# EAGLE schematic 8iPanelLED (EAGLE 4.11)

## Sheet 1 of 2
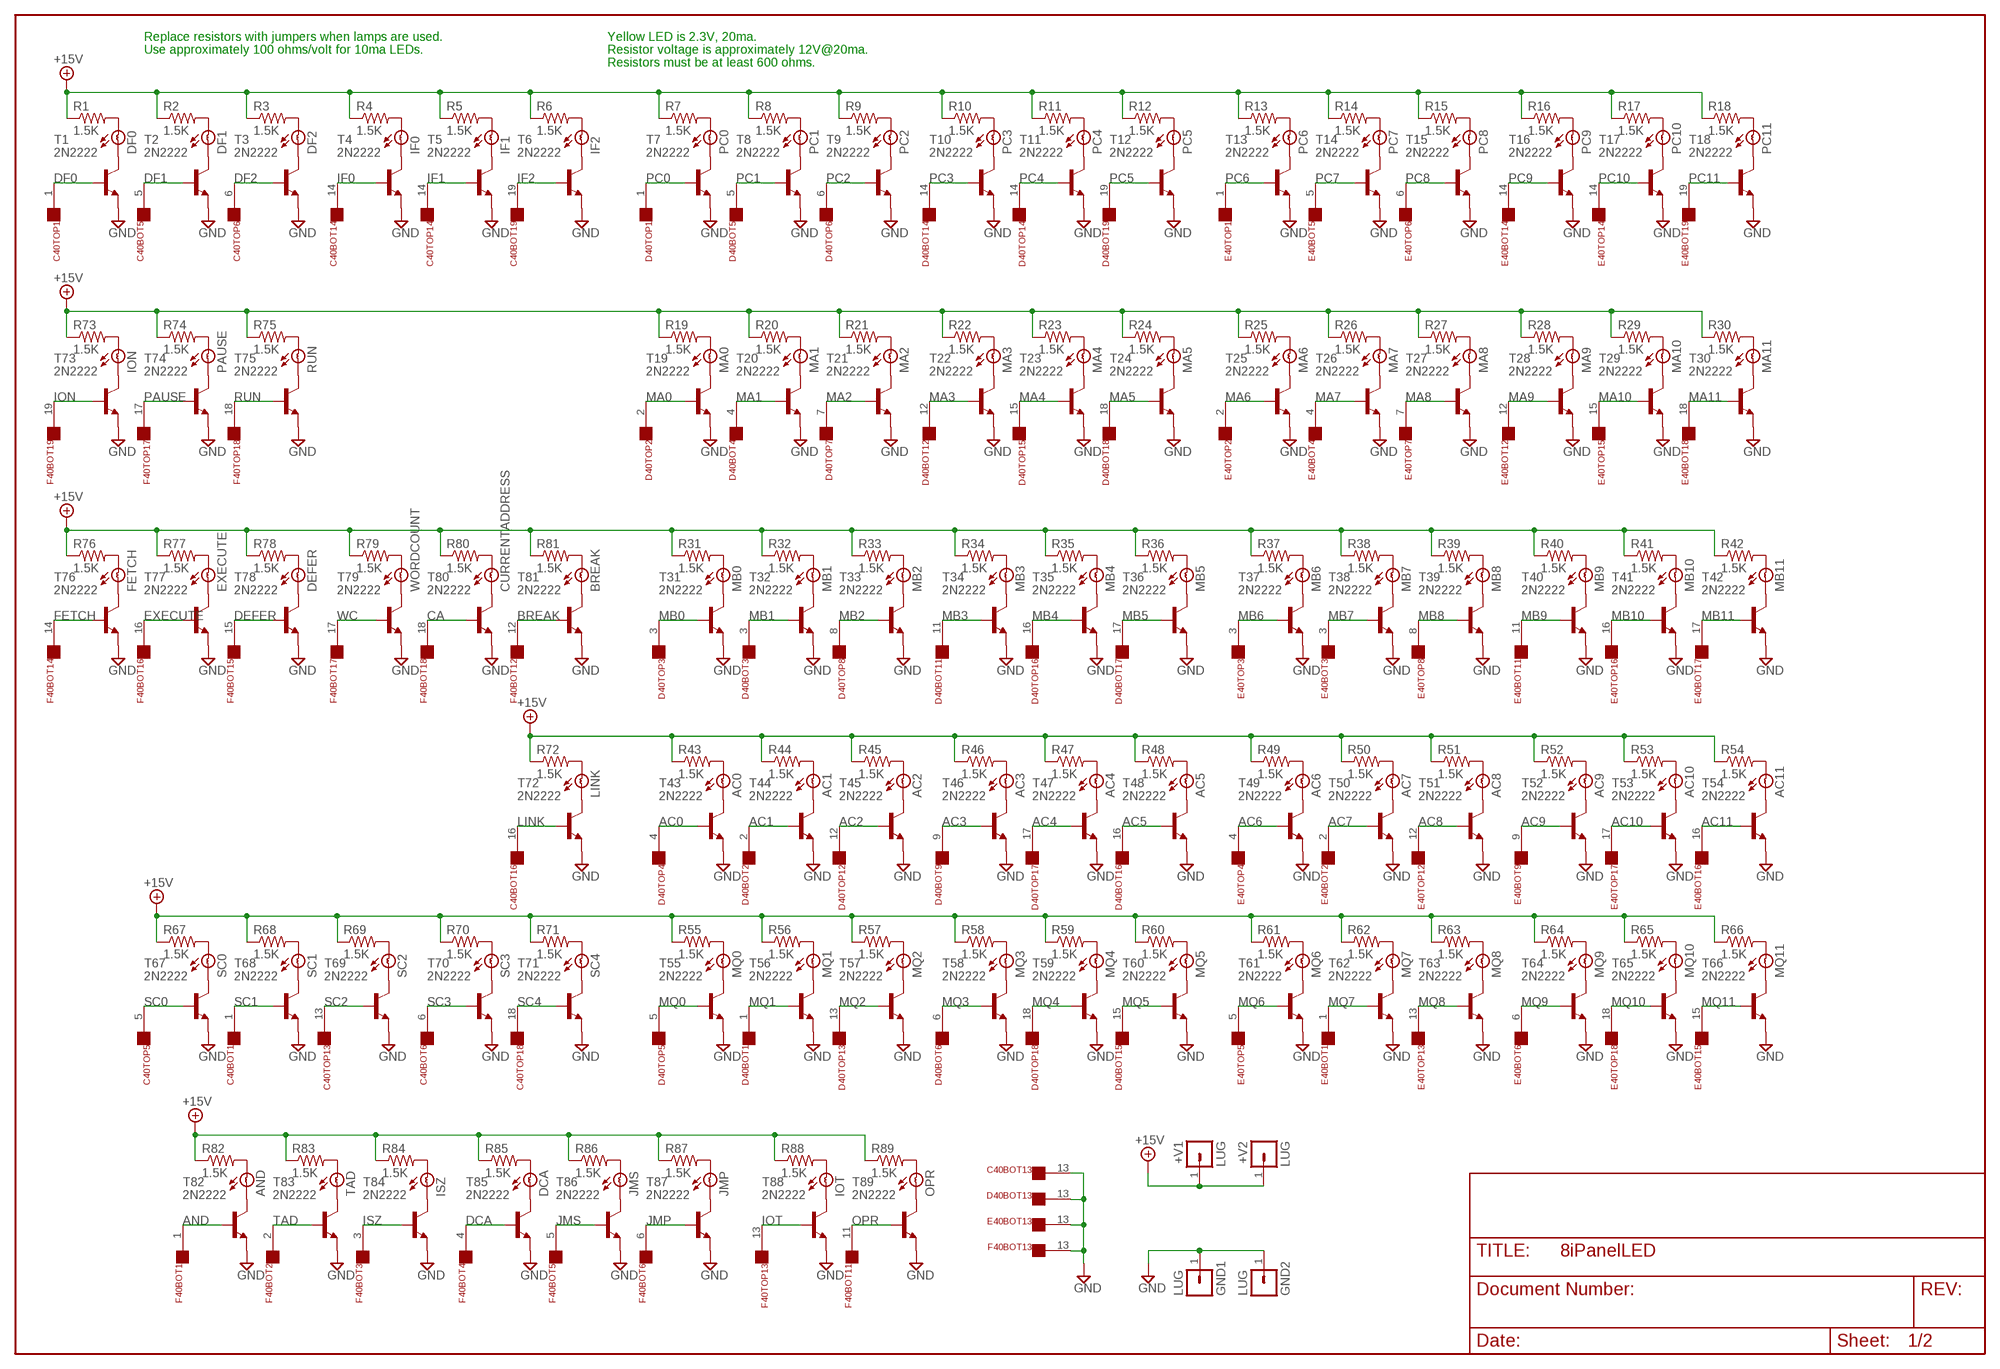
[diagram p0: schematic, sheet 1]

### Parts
+V1  LUG  [SPADELUG]
+V2  LUG  [SPADELUG]
AC0  BULB  [BULB]
AC1  BULB  [BULB]
AC2  BULB  [BULB]
AC3  BULB  [BULB]
AC4  BULB  [BULB]
AC5  BULB  [BULB]
AC6  BULB  [BULB]
AC7  BULB  [BULB]
AC8  BULB  [BULB]
AC9  BULB  [BULB]
AC10  BULB  [BULB]
AC11  BULB  [BULB]
AND  BULB  [BULB]
BREAK  BULB  [BULB]
C40BOT  FLEX19  [FLEX19]
C40TOP  FLEX19  [FLEX19]
CURRENTADDRESS  BULB  [BULB]
D40BOT  FLEX19  [FLEX19]
D40TOP  FLEX19  [FLEX19]
DCA  BULB  [BULB]
DEFER  BULB  [BULB]
DF0  BULB  [BULB]
DF1  BULB  [BULB]
DF2  BULB  [BULB]
E40BOT  FLEX19  [FLEX19]
E40TOP  FLEX19  [FLEX19]
EXECUTE  BULB  [BULB]
F40BOT  FLEX19  [FLEX19]
F40TOP  FLEX19  [FLEX19]
FETCH  BULB  [BULB]
GND1  LUG  [SPADELUG]
GND2  LUG  [SPADELUG]
IF0  BULB  [BULB]
IF1  BULB  [BULB]
IF2  BULB  [BULB]
ION  BULB  [BULB]
IOT  BULB  [BULB]
ISZ  BULB  [BULB]
JMP  BULB  [BULB]
JMS  BULB  [BULB]
LINK  BULB  [BULB]
MA0  BULB  [BULB]
MA1  BULB  [BULB]
MA2  BULB  [BULB]
MA3  BULB  [BULB]
MA4  BULB  [BULB]
MA5  BULB  [BULB]
MA6  BULB  [BULB]
MA7  BULB  [BULB]
MA8  BULB  [BULB]
MA9  BULB  [BULB]
MA10  BULB  [BULB]
MA11  BULB  [BULB]
MB0  BULB  [BULB]
MB1  BULB  [BULB]
MB2  BULB  [BULB]
MB3  BULB  [BULB]
MB4  BULB  [BULB]
MB5  BULB  [BULB]
MB6  BULB  [BULB]
MB7  BULB  [BULB]
MB8  BULB  [BULB]
MB9  BULB  [BULB]
MB10  BULB  [BULB]
MB11  BULB  [BULB]
MQ0  BULB  [BULB]
MQ1  BULB  [BULB]
MQ2  BULB  [BULB]
MQ3  BULB  [BULB]
MQ4  BULB  [BULB]
MQ5  BULB  [BULB]
MQ6  BULB  [BULB]
MQ7  BULB  [BULB]
MQ8  BULB  [BULB]
MQ9  BULB  [BULB]
MQ10  BULB  [BULB]
MQ11  BULB  [BULB]
OPR  BULB  [BULB]
PAUSE  BULB  [BULB]
PC0  BULB  [BULB]
PC1  BULB  [BULB]
PC2  BULB  [BULB]
PC3  BULB  [BULB]
PC4  BULB  [BULB]
PC5  BULB  [BULB]
PC6  BULB  [BULB]
PC7  BULB  [BULB]
PC8  BULB  [BULB]
PC9  BULB  [BULB]
PC10  BULB  [BULB]
PC11  BULB  [BULB]
R1  1.5K  R-US_0207/10  [0207/10]
R2  1.5K  R-US_0207/10  [0207/10]
R3  1.5K  R-US_0207/10  [0207/10]
R4  1.5K  R-US_0207/10  [0207/10]
R5  1.5K  R-US_0207/10  [0207/10]
R6  1.5K  R-US_0207/10  [0207/10]
R7  1.5K  R-US_0207/10  [0207/10]
R8  1.5K  R-US_0207/10  [0207/10]
R9  1.5K  R-US_0207/10  [0207/10]
R10  1.5K  R-US_0207/10  [0207/10]
R11  1.5K  R-US_0207/10  [0207/10]
R12  1.5K  R-US_0207/10  [0207/10]
R13  1.5K  R-US_0207/10  [0207/10]
R14  1.5K  R-US_0207/10  [0207/10]
R15  1.5K  R-US_0207/10  [0207/10]
R16  1.5K  R-US_0207/10  [0207/10]
R17  1.5K  R-US_0207/10  [0207/10]
R18  1.5K  R-US_0207/10  [0207/10]
R19  1.5K  R-US_0207/10  [0207/10]
R20  1.5K  R-US_0207/10  [0207/10]
R21  1.5K  R-US_0207/10  [0207/10]
R22  1.5K  R-US_0207/10  [0207/10]
R23  1.5K  R-US_0207/10  [0207/10]
R24  1.5K  R-US_0207/10  [0207/10]
R25  1.5K  R-US_0207/10  [0207/10]
R26  1.5K  R-US_0207/10  [0207/10]
R27  1.5K  R-US_0207/10  [0207/10]
R28  1.5K  R-US_0207/10  [0207/10]
R29  1.5K  R-US_0207/10  [0207/10]
R30  1.5K  R-US_0207/10  [0207/10]
R31  1.5K  R-US_0207/10  [0207/10]
R32  1.5K  R-US_0207/10  [0207/10]
R33  1.5K  R-US_0207/10  [0207/10]
R34  1.5K  R-US_0207/10  [0207/10]
R35  1.5K  R-US_0207/10  [0207/10]
R36  1.5K  R-US_0207/10  [0207/10]
R37  1.5K  R-US_0207/10  [0207/10]
R38  1.5K  R-US_0207/10  [0207/10]
R39  1.5K  R-US_0207/10  [0207/10]
R40  1.5K  R-US_0207/10  [0207/10]
R41  1.5K  R-US_0207/10  [0207/10]
R42  1.5K  R-US_0207/10  [0207/10]
R43  1.5K  R-US_0207/10  [0207/10]
R44  1.5K  R-US_0207/10  [0207/10]
R45  1.5K  R-US_0207/10  [0207/10]
R46  1.5K  R-US_0207/10  [0207/10]
R47  1.5K  R-US_0207/10  [0207/10]
R48  1.5K  R-US_0207/10  [0207/10]
R49  1.5K  R-US_0207/10  [0207/10]
R50  1.5K  R-US_0207/10  [0207/10]
R51  1.5K  R-US_0207/10  [0207/10]
R52  1.5K  R-US_0207/10  [0207/10]
R53  1.5K  R-US_0207/10  [0207/10]
R54  1.5K  R-US_0207/10  [0207/10]
R55  1.5K  R-US_0207/10  [0207/10]
R56  1.5K  R-US_0207/10  [0207/10]
R57  1.5K  R-US_0207/10  [0207/10]
R58  1.5K  R-US_0207/10  [0207/10]
R59  1.5K  R-US_0207/10  [0207/10]
R60  1.5K  R-US_0207/10  [0207/10]
R61  1.5K  R-US_0207/10  [0207/10]
R62  1.5K  R-US_0207/10  [0207/10]
R63  1.5K  R-US_0207/10  [0207/10]
R64  1.5K  R-US_0207/10  [0207/10]
R65  1.5K  R-US_0207/10  [0207/10]
R66  1.5K  R-US_0207/10  [0207/10]
R67  1.5K  R-US_0207/10  [0207/10]
R68  1.5K  R-US_0207/10  [0207/10]
R69  1.5K  R-US_0207/10  [0207/10]
R70  1.5K  R-US_0207/10  [0207/10]
R71  1.5K  R-US_0207/10  [0207/10]
R72  1.5K  R-US_0207/10  [0207/10]
R73  1.5K  R-US_0207/10  [0207/10]
R74  1.5K  R-US_0207/10  [0207/10]
R75  1.5K  R-US_0207/10  [0207/10]
R76  1.5K  R-US_0207/10  [0207/10]
R77  1.5K  R-US_0207/10  [0207/10]
R78  1.5K  R-US_0207/10  [0207/10]
R79  1.5K  R-US_0207/10  [0207/10]
R80  1.5K  R-US_0207/10  [0207/10]
R81  1.5K  R-US_0207/10  [0207/10]
R82  1.5K  R-US_0207/10  [0207/10]
R83  1.5K  R-US_0207/10  [0207/10]
R84  1.5K  R-US_0207/10  [0207/10]
R85  1.5K  R-US_0207/10  [0207/10]
R86  1.5K  R-US_0207/10  [0207/10]
R87  1.5K  R-US_0207/10  [0207/10]
R88  1.5K  R-US_0207/10  [0207/10]
R89  1.5K  R-US_0207/10  [0207/10]
RUN  BULB  [BULB]
SC0  BULB  [BULB]
SC1  BULB  [BULB]
SC2  BULB  [BULB]
SC3  BULB  [BULB]
SC4  BULB  [BULB]
T1  2N2222  -NPN-TO92  [TO92]
T2  2N2222  -NPN-TO92  [TO92]
T3  2N2222  -NPN-TO92  [TO92]
T4  2N2222  -NPN-TO92  [TO92]
T5  2N2222  -NPN-TO92  [TO92]
T6  2N2222  -NPN-TO92  [TO92]
T7  2N2222  -NPN-TO92  [TO92]
T8  2N2222  -NPN-TO92  [TO92]
T9  2N2222  -NPN-TO92  [TO92]
T10  2N2222  -NPN-TO92  [TO92]
T11  2N2222  -NPN-TO92  [TO92]
T12  2N2222  -NPN-TO92  [TO92]
T13  2N2222  -NPN-TO92  [TO92]
T14  2N2222  -NPN-TO92  [TO92]
T15  2N2222  -NPN-TO92  [TO92]
T16  2N2222  -NPN-TO92  [TO92]
T17  2N2222  -NPN-TO92  [TO92]
T18  2N2222  -NPN-TO92  [TO92]
T19  2N2222  -NPN-TO92  [TO92]
T20  2N2222  -NPN-TO92  [TO92]
T21  2N2222  -NPN-TO92  [TO92]
T22  2N2222  -NPN-TO92  [TO92]
T23  2N2222  -NPN-TO92  [TO92]
T24  2N2222  -NPN-TO92  [TO92]
T25  2N2222  -NPN-TO92  [TO92]
T26  2N2222  -NPN-TO92  [TO92]
T27  2N2222  -NPN-TO92  [TO92]
T28  2N2222  -NPN-TO92  [TO92]
T29  2N2222  -NPN-TO92  [TO92]
T30  2N2222  -NPN-TO92  [TO92]
T31  2N2222  -NPN-TO92  [TO92]
T32  2N2222  -NPN-TO92  [TO92]
T33  2N2222  -NPN-TO92  [TO92]
T34  2N2222  -NPN-TO92  [TO92]
T35  2N2222  -NPN-TO92  [TO92]
T36  2N2222  -NPN-TO92  [TO92]
T37  2N2222  -NPN-TO92  [TO92]
T38  2N2222  -NPN-TO92  [TO92]
T39  2N2222  -NPN-TO92  [TO92]
T40  2N2222  -NPN-TO92  [TO92]
T41  2N2222  -NPN-TO92  [TO92]
T42  2N2222  -NPN-TO92  [TO92]
T43  2N2222  -NPN-TO92  [TO92]
T44  2N2222  -NPN-TO92  [TO92]
T45  2N2222  -NPN-TO92  [TO92]
T46  2N2222  -NPN-TO92  [TO92]
T47  2N2222  -NPN-TO92  [TO92]
T48  2N2222  -NPN-TO92  [TO92]
T49  2N2222  -NPN-TO92  [TO92]
T50  2N2222  -NPN-TO92  [TO92]
T51  2N2222  -NPN-TO92  [TO92]
T52  2N2222  -NPN-TO92  [TO92]
T53  2N2222  -NPN-TO92  [TO92]
T54  2N2222  -NPN-TO92  [TO92]
T55  2N2222  -NPN-TO92  [TO92]
T56  2N2222  -NPN-TO92  [TO92]
T57  2N2222  -NPN-TO92  [TO92]
T58  2N2222  -NPN-TO92  [TO92]
T59  2N2222  -NPN-TO92  [TO92]
T60  2N2222  -NPN-TO92  [TO92]
T61  2N2222  -NPN-TO92  [TO92]
T62  2N2222  -NPN-TO92  [TO92]
T63  2N2222  -NPN-TO92  [TO92]
T64  2N2222  -NPN-TO92  [TO92]
T65  2N2222  -NPN-TO92  [TO92]
T66  2N2222  -NPN-TO92  [TO92]
T67  2N2222  -NPN-TO92  [TO92]
T68  2N2222  -NPN-TO92  [TO92]
T69  2N2222  -NPN-TO92  [TO92]
T70  2N2222  -NPN-TO92  [TO92]
T71  2N2222  -NPN-TO92  [TO92]
T72  2N2222  -NPN-TO92  [TO92]
T73  2N2222  -NPN-TO92  [TO92]
T74  2N2222  -NPN-TO92  [TO92]
T75  2N2222  -NPN-TO92  [TO92]
T76  2N2222  -NPN-TO92  [TO92]
T77  2N2222  -NPN-TO92  [TO92]
T78  2N2222  -NPN-TO92  [TO92]
T79  2N2222  -NPN-TO92  [TO92]
T80  2N2222  -NPN-TO92  [TO92]
T81  2N2222  -NPN-TO92  [TO92]
T82  2N2222  -NPN-TO92  [TO92]
T83  2N2222  -NPN-TO92  [TO92]
T84  2N2222  -NPN-TO92  [TO92]
T85  2N2222  -NPN-TO92  [TO92]
T86  2N2222  -NPN-TO92  [TO92]
T87  2N2222  -NPN-TO92  [TO92]
T88  2N2222  -NPN-TO92  [TO92]
T89  2N2222  -NPN-TO92  [TO92]
TAD  BULB  [BULB]
WORDCOUNT  BULB  [BULB]

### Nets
+15V [supply]: +V1.1 +V2.1 R1.1 R2.1 R3.1 R4.1 R5.1 R6.1 R7.1 R8.1 R9.1 R10.1 R11.1 R12.1 R13.1 R14.1 R15.1 R16.1 R17.1 R18.1 R19.1 R20.1 R21.1 R22.1 R23.1 R24.1 R25.1 R26.1 R27.1 R28.1 R29.1 R30.1 R31.1 R32.1 R33.1 R34.1 R35.1 R36.1 R37.1 R38.1 R39.1 R40.1 R41.1 R42.1 R43.1 R44.1 R45.1 R46.1 R47.1 R48.1 R49.1 R50.1 R51.1 R52.1 R53.1 R54.1 R55.1 R56.1 R57.1 R58.1 R59.1 R60.1 R61.1 R62.1 R63.1 R64.1 R65.1 R66.1 R67.1 R68.1 R69.1 R70.1 R71.1 R72.1 R73.1 R74.1 R75.1 R76.1 R77.1 R78.1 R79.1 R80.1 R81.1 R82.1 R83.1 R84.1 R85.1 R86.1 R87.1 R88.1 R89.1
AC0: D40TOP.4 T43.2(B) ; also sheet 2
AC1: D40BOT.2 T44.2(B) ; also sheet 2
AC2: D40TOP.12 T45.2(B) ; also sheet 2
AC3: D40BOT.9 T46.2(B) ; also sheet 2
AC4: D40TOP.17 T47.2(B) ; also sheet 2
AC5: D40BOT.16 T48.2(B) ; also sheet 2
AC6: E40TOP.4 T49.2(B) ; also sheet 2
AC7: E40BOT.2 T50.2(B) ; also sheet 2
AC8: E40TOP.12 T51.2(B) ; also sheet 2
AC9: E40BOT.9 T52.2(B) ; also sheet 2
AC10: E40TOP.17 T53.2(B) ; also sheet 2
AC11: E40BOT.16 T54.2(B) ; also sheet 2
AND: F40BOT.1 T82.2(B) ; also sheet 2
BREAK: F40BOT.12 T81.2(B) ; also sheet 2
CA: F40BOT.18 T80.2(B) ; also sheet 2
DCA: F40BOT.4 T85.2(B) ; also sheet 2
DEFER: F40BOT.15 T78.2(B) ; also sheet 2
DF0: C40TOP.1 T1.2(B) ; also sheet 2
DF1: C40BOT.5 T2.2(B) ; also sheet 2
DF2: C40TOP.6 T3.2(B) ; also sheet 2
EXECUTE: F40BOT.16 T77.2(B) ; also sheet 2
FETCH: F40BOT.14 T76.2(B) ; also sheet 2
GND [supply]: C40BOT.13 D40BOT.13 E40BOT.13 F40BOT.13 GND1.1 GND2.1 T1.1(E) T2.1(E) T3.1(E) T4.1(E) T5.1(E) T6.1(E) T7.1(E) T8.1(E) T9.1(E) T10.1(E) T11.1(E) T12.1(E) T13.1(E) T14.1(E) T15.1(E) T16.1(E) T17.1(E) T18.1(E) T19.1(E) T20.1(E) T21.1(E) T22.1(E) T23.1(E) T24.1(E) T25.1(E) T26.1(E) T27.1(E) T28.1(E) T29.1(E) T30.1(E) T31.1(E) T32.1(E) T33.1(E) T34.1(E) T35.1(E) T36.1(E) T37.1(E) T38.1(E) T39.1(E) T40.1(E) T41.1(E) T42.1(E) T43.1(E) T44.1(E) T45.1(E) T46.1(E) T47.1(E) T48.1(E) T49.1(E) T50.1(E) T51.1(E) T52.1(E) T53.1(E) T54.1(E) T55.1(E) T56.1(E) T57.1(E) T58.1(E) T59.1(E) T60.1(E) T61.1(E) T62.1(E) T63.1(E) T64.1(E) T65.1(E) T66.1(E) T67.1(E) T68.1(E) T69.1(E) T70.1(E) T71.1(E) T72.1(E) T73.1(E) T74.1(E) T75.1(E) T76.1(E) T77.1(E) T78.1(E) T79.1(E) T80.1(E) T81.1(E) T82.1(E) T83.1(E) T84.1(E) T85.1(E) T86.1(E) T87.1(E) T88.1(E) T89.1(E) ; also sheet 2
IF0: C40BOT.14 T4.2(B) ; also sheet 2
IF1: C40TOP.14 T5.2(B) ; also sheet 2
IF2: C40BOT.19 T6.2(B) ; also sheet 2
ION: F40BOT.19 T73.2(B) ; also sheet 2
IOT: F40TOP.13 T88.2(B) ; also sheet 2
ISZ: F40BOT.3 T84.2(B) ; also sheet 2
JMP: F40BOT.6 T87.2(B) ; also sheet 2
JMS: F40BOT.5 T86.2(B) ; also sheet 2
LINK: C40BOT.16 T72.2(B) ; also sheet 2
MA0: D40TOP.2 T19.2(B) ; also sheet 2
MA1: D40BOT.4 T20.2(B) ; also sheet 2
MA2: D40TOP.7 T21.2(B) ; also sheet 2
MA3: D40BOT.12 T22.2(B) ; also sheet 2
MA4: D40TOP.15 T23.2(B) ; also sheet 2
MA5: D40BOT.18 T24.2(B) ; also sheet 2
MA6: E40TOP.2 T25.2(B) ; also sheet 2
MA7: E40BOT.4 T26.2(B) ; also sheet 2
MA8: E40TOP.7 T27.2(B) ; also sheet 2
MA9: E40BOT.12 T28.2(B) ; also sheet 2
MA10: E40TOP.15 T29.2(B) ; also sheet 2
MA11: E40BOT.18 T30.2(B) ; also sheet 2
MB0: D40TOP.3 T31.2(B) ; also sheet 2
MB1: D40BOT.3 T32.2(B) ; also sheet 2
MB2: D40TOP.8 T33.2(B) ; also sheet 2
MB3: D40BOT.11 T34.2(B) ; also sheet 2
MB4: D40TOP.16 T35.2(B) ; also sheet 2
MB5: D40BOT.17 T36.2(B) ; also sheet 2
MB6: E40TOP.3 T37.2(B) ; also sheet 2
MB7: E40BOT.3 T38.2(B) ; also sheet 2
MB8: E40TOP.8 T39.2(B) ; also sheet 2
MB9: E40BOT.11 T40.2(B) ; also sheet 2
MB10: E40TOP.16 T41.2(B) ; also sheet 2
MB11: E40BOT.17 T42.2(B) ; also sheet 2
MQ0: D40TOP.5 T55.2(B) ; also sheet 2
MQ1: D40BOT.1 T56.2(B) ; also sheet 2
MQ2: D40TOP.13 T57.2(B) ; also sheet 2
MQ3: D40BOT.6 T58.2(B) ; also sheet 2
MQ4: D40TOP.18 T59.2(B) ; also sheet 2
MQ5: D40BOT.15 T60.2(B) ; also sheet 2
MQ6: E40TOP.5 T61.2(B) ; also sheet 2
MQ7: E40BOT.1 T62.2(B) ; also sheet 2
MQ8: E40TOP.13 T63.2(B) ; also sheet 2
MQ9: E40BOT.6 T64.2(B) ; also sheet 2
MQ10: E40TOP.18 T65.2(B) ; also sheet 2
MQ11: E40BOT.15 T66.2(B) ; also sheet 2
N$1: DF0.B T1.3(C)
N$2: DF1.B T2.3(C)
N$3: DF2.B T3.3(C)
N$4: IF0.B T4.3(C)
N$5: IF1.B T5.3(C)
N$6: IF2.B T6.3(C)
N$7: PC0.B T7.3(C)
N$8: PC1.B T8.3(C)
N$9: PC2.B T9.3(C)
N$10: PC3.B T10.3(C)
N$11: PC4.B T11.3(C)
N$12: PC5.B T12.3(C)
N$13: PC6.B T13.3(C)
N$14: PC7.B T14.3(C)
N$15: PC8.B T15.3(C)
N$16: PC9.B T16.3(C)
N$17: PC10.B T17.3(C)
N$18: PC11.B T18.3(C)
N$19: MA0.B T19.3(C)
N$20: MA1.B T20.3(C)
N$21: MA2.B T21.3(C)
N$22: MA3.B T22.3(C)
N$23: MA4.B T23.3(C)
N$24: MA5.B T24.3(C)
N$25: MA6.B T25.3(C)
N$26: MA7.B T26.3(C)
N$27: MA8.B T27.3(C)
N$28: MA9.B T28.3(C)
N$29: MA10.B T29.3(C)
N$30: MA11.B T30.3(C)
N$31: MB0.B T31.3(C)
N$32: MB1.B T32.3(C)
N$33: MB2.B T33.3(C)
N$34: MB3.B T34.3(C)
N$35: MB4.B T35.3(C)
N$36: MB5.B T36.3(C)
N$37: MB6.B T37.3(C)
N$38: MB7.B T38.3(C)
N$39: MB8.B T39.3(C)
N$40: MB9.B T40.3(C)
N$41: MB10.B T41.3(C)
N$42: MB11.B T42.3(C)
N$43: AC0.B T43.3(C)
N$44: AC1.B T44.3(C)
N$45: AC2.B T45.3(C)
N$46: AC3.B T46.3(C)
N$47: AC4.B T47.3(C)
N$48: AC5.B T48.3(C)
N$49: AC6.B T49.3(C)
N$50: AC7.B T50.3(C)
N$51: AC8.B T51.3(C)
N$52: AC9.B T52.3(C)
N$53: AC10.B T53.3(C)
N$54: AC11.B T54.3(C)
N$55: MQ0.B T55.3(C)
N$56: MQ1.B T56.3(C)
N$57: MQ2.B T57.3(C)
N$58: MQ3.B T58.3(C)
N$59: MQ4.B T59.3(C)
N$60: MQ5.B T60.3(C)
N$61: MQ6.B T61.3(C)
N$62: MQ7.B T62.3(C)
N$63: MQ8.B T63.3(C)
N$64: MQ9.B T64.3(C)
N$65: MQ10.B T65.3(C)
N$66: MQ11.B T66.3(C)
N$67: SC0.B T67.3(C)
N$68: SC1.B T68.3(C)
N$69: SC2.B T69.3(C)
N$70: SC3.B T70.3(C)
N$71: SC4.B T71.3(C)
N$72: LINK.B T72.3(C)
N$73: ION.B T73.3(C)
N$74: PAUSE.B T74.3(C)
N$75: RUN.B T75.3(C)
N$76: FETCH.B T76.3(C)
N$77: EXECUTE.B T77.3(C)
N$78: DEFER.B T78.3(C)
N$79: T79.3(C) WORDCOUNT.B
N$80: CURRENTADDRESS.B T80.3(C)
N$81: BREAK.B T81.3(C)
N$82: AND.B T82.3(C)
N$83: T83.3(C) TAD.B
N$84: ISZ.B T84.3(C)
N$85: DCA.B T85.3(C)
N$86: JMS.B T86.3(C)
N$87: JMP.B T87.3(C)
N$88: IOT.B T88.3(C)
N$89: OPR.B T89.3(C)
N$90: DF0.A R1.2
N$91: DF1.A R2.2
N$92: DF2.A R3.2
N$93: IF0.A R4.2
N$94: IF1.A R5.2
N$95: IF2.A R6.2
N$96: PC0.A R7.2
N$97: PC1.A R8.2
N$98: PC2.A R9.2
N$99: PC3.A R10.2
N$100: PC4.A R11.2
N$101: PC5.A R12.2
N$102: PC6.A R13.2
N$103: PC7.A R14.2
N$104: PC8.A R15.2
N$105: PC9.A R16.2
N$106: PC10.A R17.2
N$107: PC11.A R18.2
N$108: ION.A R73.2
N$109: PAUSE.A R74.2
N$110: R75.2 RUN.A
N$111: MA0.A R19.2
N$112: MA1.A R20.2
N$113: MA2.A R21.2
N$114: MA3.A R22.2
N$115: MA4.A R23.2
N$116: MA5.A R24.2
N$117: MA6.A R25.2
N$118: MA7.A R26.2
N$119: MA8.A R27.2
N$120: MA9.A R28.2
N$121: MA10.A R29.2
N$122: MA11.A R30.2
N$123: FETCH.A R76.2
N$124: EXECUTE.A R77.2
N$125: DEFER.A R78.2
N$126: R79.2 WORDCOUNT.A
N$127: CURRENTADDRESS.A R80.2
N$128: BREAK.A R81.2
N$129: LINK.A R72.2
N$130: MB0.A R31.2
N$131: MB1.A R32.2
N$132: MB2.A R33.2
N$133: MB3.A R34.2
N$134: MB4.A R35.2
N$135: MB5.A R36.2
N$136: MB6.A R37.2
N$137: MB7.A R38.2
N$138: MB8.A R39.2
N$139: MB9.A R40.2
N$140: MB10.A R41.2
N$141: MB11.A R42.2
N$142: AC0.A R43.2
N$143: AC1.A R44.2
N$144: AC2.A R45.2
N$145: AC3.A R46.2
N$146: AC4.A R47.2
N$147: AC5.A R48.2
N$148: AC6.A R49.2
N$149: AC7.A R50.2
N$150: AC8.A R51.2
N$151: AC9.A R52.2
N$152: AC10.A R53.2
N$153: AC11.A R54.2
N$154: R67.2 SC0.A
N$155: R68.2 SC1.A
N$156: R69.2 SC2.A
N$157: R70.2 SC3.A
N$158: R71.2 SC4.A
N$159: MQ11.A R66.2
N$160: MQ10.A R65.2
N$161: MQ9.A R64.2
N$162: MQ8.A R63.2
N$163: MQ7.A R62.2
N$164: MQ6.A R61.2
N$165: MQ5.A R60.2
N$166: MQ4.A R59.2
N$167: MQ3.A R58.2
N$168: MQ2.A R57.2
N$169: MQ1.A R56.2
N$170: MQ0.A R55.2
N$171: AND.A R82.2
N$172: R83.2 TAD.A
N$173: ISZ.A R84.2
N$174: DCA.A R85.2
N$175: JMS.A R86.2
N$176: JMP.A R87.2
N$177: IOT.A R88.2
N$178: OPR.A R89.2
OPR: F40BOT.11 T89.2(B) ; also sheet 2
PAUSE: F40TOP.17 T74.2(B) ; also sheet 2
PC0: D40TOP.1 T7.2(B) ; also sheet 2
PC1: D40BOT.5 T8.2(B) ; also sheet 2
PC2: D40TOP.6 T9.2(B) ; also sheet 2
PC3: D40BOT.14 T10.2(B) ; also sheet 2
PC4: D40TOP.14 T11.2(B) ; also sheet 2
PC5: D40BOT.19 T12.2(B) ; also sheet 2
PC6: E40TOP.1 T13.2(B) ; also sheet 2
PC7: E40BOT.5 T14.2(B) ; also sheet 2
PC8: E40TOP.6 T15.2(B) ; also sheet 2
PC9: E40BOT.14 T16.2(B) ; also sheet 2
PC10: E40TOP.14 T17.2(B) ; also sheet 2
PC11: E40BOT.19 T18.2(B) ; also sheet 2
RUN: F40TOP.18 T75.2(B) ; also sheet 2
SC0: C40TOP.5 T67.2(B) ; also sheet 2
SC1: C40BOT.1 T68.2(B) ; also sheet 2
SC2: C40TOP.13 T69.2(B) ; also sheet 2
SC3: C40BOT.6 T70.2(B) ; also sheet 2
SC4: C40TOP.18 T71.2(B) ; also sheet 2
TAD: F40BOT.2 T83.2(B) ; also sheet 2
WC: F40BOT.17 T79.2(B) ; also sheet 2
Unconnected: C40BOT.2 C40BOT.3 C40BOT.4 C40BOT.7 C40BOT.8 C40BOT.9 C40BOT.10 C40BOT.11 C40BOT.12 C40BOT.15 C40BOT.17 C40BOT.18 C40TOP.2 C40TOP.3 C40TOP.4 C40TOP.7 C40TOP.8 C40TOP.9 C40TOP.10 C40TOP.11 C40TOP.12 C40TOP.15 C40TOP.16 C40TOP.17 C40TOP.19 D40BOT.7 D40BOT.8 D40BOT.10 D40TOP.9 D40TOP.10 D40TOP.11 D40TOP.19 E40BOT.7 E40BOT.8 E40BOT.10 E40TOP.9 E40TOP.10 E40TOP.11 E40TOP.19 F40BOT.7 F40BOT.8 F40BOT.9 F40BOT.10 F40TOP.1 F40TOP.2 F40TOP.3 F40TOP.4 F40TOP.5 F40TOP.6 F40TOP.7 F40TOP.8 F40TOP.9 F40TOP.10 F40TOP.11 F40TOP.12 F40TOP.14 F40TOP.15 F40TOP.16 F40TOP.19

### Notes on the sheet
- Replace resistors with jumpers when lamps are used. | Yellow LED is 2.3V, 20ma.
- Use approximately 100 ohms/volt for 10ma LEDs. | Resistor voltage is approximately 12V@20ma.
- Resistors must be at least 600 ohms.

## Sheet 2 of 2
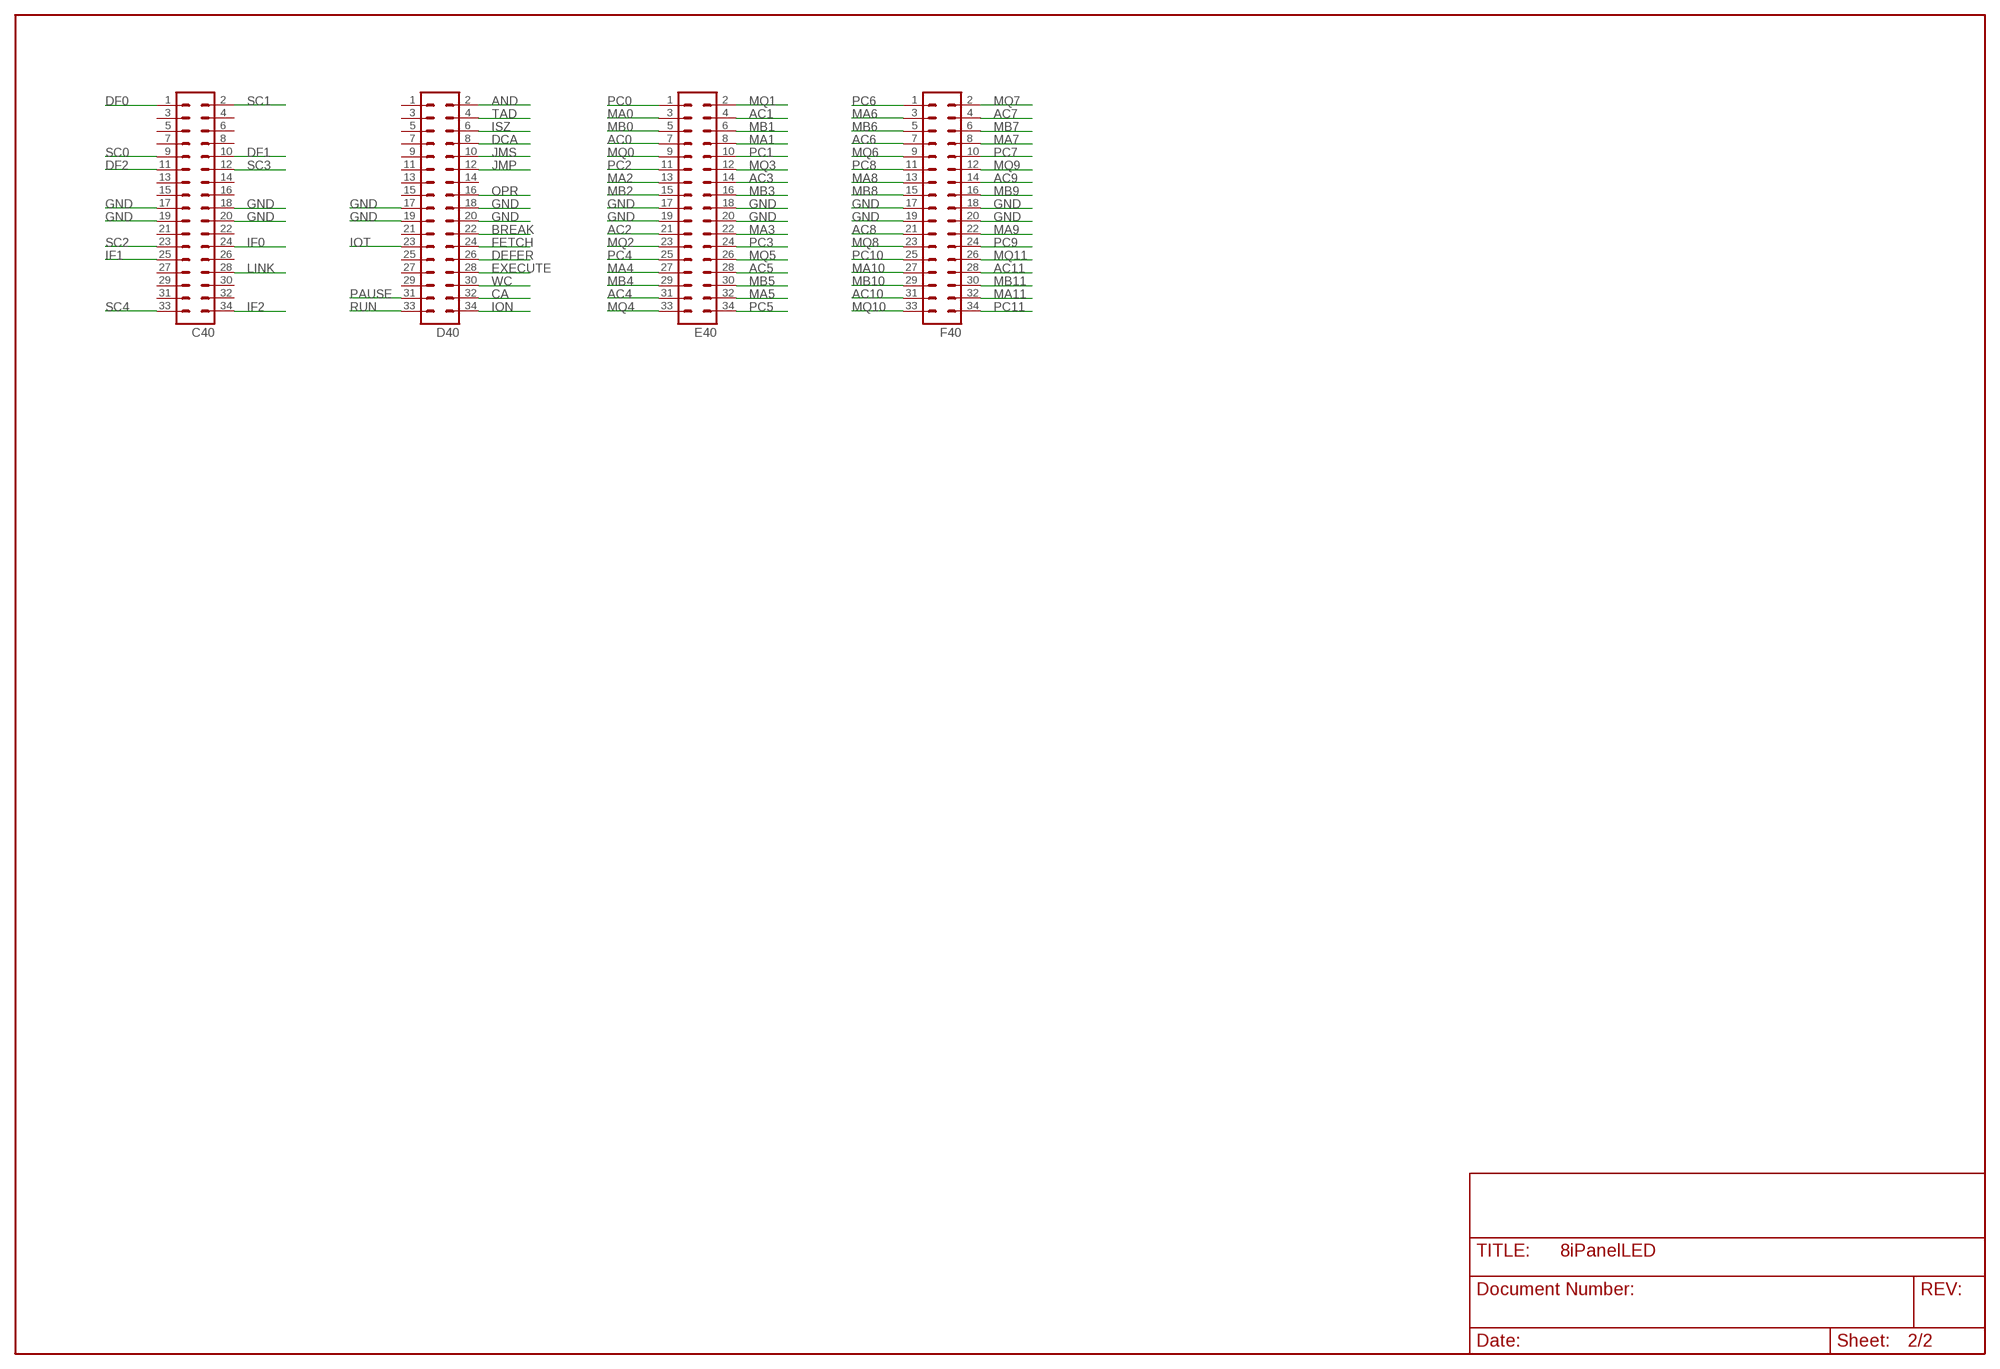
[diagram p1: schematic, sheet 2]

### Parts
C40  MA17-2  [MA17-2]
D40  MA17-2  [MA17-2]
E40  MA17-2  [MA17-2]
F40  MA17-2  [MA17-2]

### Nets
AC0: E40.7 ; also sheet 1
AC1: E40.4 ; also sheet 1
AC2: E40.21 ; also sheet 1
AC3: E40.14 ; also sheet 1
AC4: E40.31 ; also sheet 1
AC5: E40.28 ; also sheet 1
AC6: F40.7 ; also sheet 1
AC7: F40.4 ; also sheet 1
AC8: F40.21 ; also sheet 1
AC9: F40.14 ; also sheet 1
AC10: F40.31 ; also sheet 1
AC11: F40.28 ; also sheet 1
AND: D40.2 ; also sheet 1
BREAK: D40.22 ; also sheet 1
CA: D40.32 ; also sheet 1
DCA: D40.8 ; also sheet 1
DEFER: D40.26 ; also sheet 1
DF0: C40.1 ; also sheet 1
DF1: C40.10 ; also sheet 1
DF2: C40.11 ; also sheet 1
EXECUTE: D40.28 ; also sheet 1
FETCH: D40.24 ; also sheet 1
GND [supply]: C40.17 C40.18 C40.19 C40.20 D40.17 D40.18 D40.19 D40.20 E40.17 E40.18 E40.19 E40.20 F40.17 F40.18 F40.19 F40.20 ; also sheet 1
IF0: C40.24 ; also sheet 1
IF1: C40.25 ; also sheet 1
IF2: C40.34 ; also sheet 1
ION: D40.34 ; also sheet 1
IOT: D40.23 ; also sheet 1
ISZ: D40.6 ; also sheet 1
JMP: D40.12 ; also sheet 1
JMS: D40.10 ; also sheet 1
LINK: C40.28 ; also sheet 1
MA0: E40.3 ; also sheet 1
MA1: E40.8 ; also sheet 1
MA2: E40.13 ; also sheet 1
MA3: E40.22 ; also sheet 1
MA4: E40.27 ; also sheet 1
MA5: E40.32 ; also sheet 1
MA6: F40.3 ; also sheet 1
MA7: F40.8 ; also sheet 1
MA8: F40.13 ; also sheet 1
MA9: F40.22 ; also sheet 1
MA10: F40.27 ; also sheet 1
MA11: F40.32 ; also sheet 1
MB0: E40.5 ; also sheet 1
MB1: E40.6 ; also sheet 1
MB2: E40.15 ; also sheet 1
MB3: E40.16 ; also sheet 1
MB4: E40.29 ; also sheet 1
MB5: E40.30 ; also sheet 1
MB6: F40.5 ; also sheet 1
MB7: F40.6 ; also sheet 1
MB8: F40.15 ; also sheet 1
MB9: F40.16 ; also sheet 1
MB10: F40.29 ; also sheet 1
MB11: F40.30 ; also sheet 1
MQ0: E40.9 ; also sheet 1
MQ1: E40.2 ; also sheet 1
MQ2: E40.23 ; also sheet 1
MQ3: E40.12 ; also sheet 1
MQ4: E40.33 ; also sheet 1
MQ5: E40.26 ; also sheet 1
MQ6: F40.9 ; also sheet 1
MQ7: F40.2 ; also sheet 1
MQ8: F40.23 ; also sheet 1
MQ9: F40.12 ; also sheet 1
MQ10: F40.33 ; also sheet 1
MQ11: F40.26 ; also sheet 1
OPR: D40.16 ; also sheet 1
PAUSE: D40.31 ; also sheet 1
PC0: E40.1 ; also sheet 1
PC1: E40.10 ; also sheet 1
PC2: E40.11 ; also sheet 1
PC3: E40.24 ; also sheet 1
PC4: E40.25 ; also sheet 1
PC5: E40.34 ; also sheet 1
PC6: F40.1 ; also sheet 1
PC7: F40.10 ; also sheet 1
PC8: F40.11 ; also sheet 1
PC9: F40.24 ; also sheet 1
PC10: F40.25 ; also sheet 1
PC11: F40.34 ; also sheet 1
RUN: D40.33 ; also sheet 1
SC0: C40.9 ; also sheet 1
SC1: C40.2 ; also sheet 1
SC2: C40.23 ; also sheet 1
SC3: C40.12 ; also sheet 1
SC4: C40.33 ; also sheet 1
TAD: D40.4 ; also sheet 1
WC: D40.30 ; also sheet 1
Unconnected: C40.3 C40.4 C40.5 C40.6 C40.7 C40.8 C40.13 C40.14 C40.15 C40.16 C40.21 C40.22 C40.26 C40.27 C40.29 C40.30 C40.31 C40.32 D40.1 D40.3 D40.5 D40.7 D40.9 D40.11 D40.13 D40.14 D40.15 D40.21 D40.25 D40.27 D40.29

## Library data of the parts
+V1 +V2 GND1 GND2 = dec-con:LUG: Spade Lug
AC0 AC1-AC11 AND BREAK CURRENTADDRESS DCA DEFER DF0 DF1 DF2 EXECUTE FETCH IF0 IF1 IF2 ION IOT ISZ JMP JMS LINK MA0 MA1-MA11 MB0 MB1-MB11 MQ0 MQ1-MQ11 OPR PAUSE PC0 PC1-PC11 RUN SC0 SC1-SC4 TAD WORDCOUNT = dec-con:BULB: T 1 3/4 Bulb
C40 D40 E40 F40 = con-lstb:MA17-2: PIN HEADER
C40BOT C40TOP D40BOT D40TOP E40BOT E40TOP F40BOT F40TOP = dec-con:FLEX19
R1-R89 = rcl:R-US_: RESISTOR, American symbol
T1-T89 = transistor:*-NPN-: NPN Transistror

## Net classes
1 supply: width 0.762 mm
